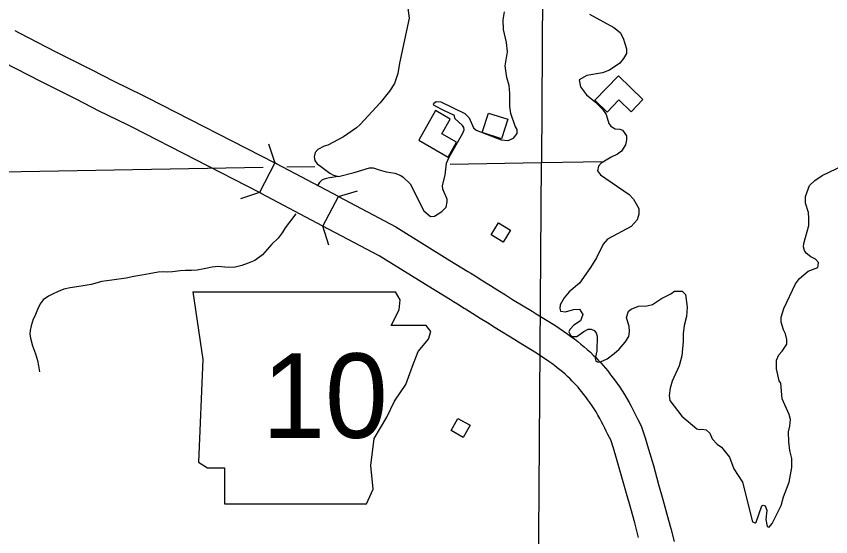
# Model space of a CAD drawing. Extents: x -19 to 366, y -4 to 359.
# Drawn here: x 137.635 to 138.792, y 198.536 to 199.276 of the extents above; entities that cross this region are included whole.
import ezdxf

# ---------------------------------------------------------------- set-up
doc = ezdxf.new("R2010")
doc.units = 0
for name, color, linetype in [('Level 10', 7, 'Continuous'), ('Level 21', 7, 'Continuous'), ('Level 35', 7, 'Continuous'), ('Level 37', 7, 'Continuous'), ('Level 5', 7, 'Continuous'), ('Level 56', 7, 'Continuous'), ('Level 57', 7, 'Continuous'), ('Level 60', 7, 'Continuous'), ('Level 9', 7, 'Continuous')]:
    doc.layers.add(name, color=color, linetype=linetype)

msp = doc.modelspace()

# ---------------------------------------------------------------- linework, layer by layer
at = {"layer": 'Level 10'}
for p, q in [((138.0017, 199.0671), (137.9801, 199.025)), ((138.0702, 198.9774), (138.0924, 199.0193)), ((138.2506, 198.9286), (138.2761, 198.913)), ((138.2761, 198.913), (138.2805, 198.9104)), ((138.2515, 198.8726), (138.226, 198.8881)), ((138.2557, 198.87), (138.2515, 198.8726))]:
    msp.add_line(p, q, dxfattribs=at)
for points in [[(137.6326, 199.2552), (137.6386, 199.252), (137.6909, 199.2251), (137.7418, 199.1993), (137.7733, 199.1833), (137.8137, 199.1635), (137.8206, 199.16), (138.0017, 199.0671)], [(137.9801, 199.025), (137.7991, 199.1178), (137.7925, 199.1211), (137.7522, 199.1409), (137.7204, 199.1571), (137.6694, 199.183), (137.6167, 199.21)], [(138.0924, 199.0193), (138.0043, 199.0658), (138.0017, 199.0671)], [(138.0702, 198.9774), (137.9825, 199.0238), (137.9801, 199.025)], [(138.0924, 199.0193), (138.174, 198.9762), (138.2506, 198.9286)], [(138.226, 198.8881), (138.1504, 198.9351), (138.0702, 198.9774)], [(138.2805, 198.9104), (138.2865, 198.9067), (138.2959, 198.9008)], [(138.2959, 198.9008), (138.2977, 198.8997), (138.3083, 198.8932), (138.3189, 198.8865), (138.3295, 198.8799), (138.3399, 198.8734), (138.3677, 198.8564), (138.3733, 198.853), (138.3996, 198.8366), (138.4181, 198.824), (138.4228, 198.8207), (138.4276, 198.8173), (138.4324, 198.8137), (138.437, 198.8099), (138.4416, 198.8061), (138.446, 198.8022), (138.4504, 198.7982), (138.4545, 198.7942), (138.458, 198.7907), (138.4616, 198.7871), (138.4651, 198.7833), (138.4685, 198.7795), (138.4718, 198.7757), (138.475, 198.7717), (138.4782, 198.7677), (138.481, 198.7639), (138.4846, 198.7592), (138.4884, 198.754), (138.492, 198.7488), (138.4955, 198.7435), (138.4989, 198.738), (138.5021, 198.7325), (138.5053, 198.727), (138.5082, 198.7215), (138.5106, 198.7168), (138.513, 198.7121), (138.5153, 198.7074), (138.5177, 198.7028), (138.52, 198.6982), (138.5229, 198.6922), (138.5284, 198.6764), (138.5331, 198.6607), (138.5399, 198.6371), (138.5473, 198.6102), (138.5532, 198.5888), (138.5589, 198.5684), (138.5646, 198.5476), (138.5695, 198.5293)], [(138.2711, 198.8605), (138.2616, 198.8664), (138.2557, 198.87)], [(138.5189, 198.5351), (138.5133, 198.5558), (138.5076, 198.5761), (138.5017, 198.5976), (138.4943, 198.6243), (138.4877, 198.6473), (138.4833, 198.6618), (138.4792, 198.6739), (138.4776, 198.6771), (138.4753, 198.6816), (138.473, 198.6861), (138.4708, 198.6906), (138.4685, 198.6951), (138.4662, 198.6995), (138.4637, 198.7043), (138.4611, 198.7089), (138.4584, 198.7135), (138.4557, 198.7179), (138.4527, 198.7223), (138.4498, 198.7266), (138.4467, 198.7308), (138.4433, 198.7353), (138.4406, 198.7389), (138.4381, 198.7421), (138.4355, 198.7453), (138.4328, 198.7484), (138.4301, 198.7514), (138.4274, 198.7543), (138.4245, 198.7573), (138.4214, 198.7603), (138.4178, 198.7638), (138.4143, 198.767), (138.4107, 198.7702), (138.407, 198.7733), (138.4033, 198.7763), (138.3994, 198.7792), (138.3955, 198.7821), (138.3913, 198.7849), (138.3738, 198.797), (138.3483, 198.8127), (138.3429, 198.8161), (138.315, 198.8331), (138.3043, 198.8398), (138.2938, 198.8464), (138.2833, 198.853), (138.2728, 198.8595), (138.2711, 198.8605)]]:
    msp.add_lwpolyline(points, dxfattribs=at)
at = {"layer": 'Level 21'}
for p, q in [((137.8853, 198.884), (137.8997, 198.7879)), ((138.1801, 198.8728), (138.1735, 198.8839)), ((138.1785, 198.8584), (138.1801, 198.8728)), ((138.1673, 198.836), (138.1785, 198.8584)), ((138.217, 198.836), (138.1673, 198.836)), ((138.2234, 198.8279), (138.217, 198.836)), ((138.2202, 198.8167), (138.2234, 198.8279)), ((138.2057, 198.7991), (138.2202, 198.8167)), ((137.8997, 198.7879), (137.8933, 198.6421)), ((138.1977, 198.7783), (138.2057, 198.7991)), ((138.1881, 198.7526), (138.1977, 198.7783)), ((138.1721, 198.7286), (138.1881, 198.7526)), ((138.1609, 198.7062), (138.1721, 198.7286)), ((138.1433, 198.6757), (138.1609, 198.7062)), ((138.1385, 198.6373), (138.1433, 198.6757)), ((137.8933, 198.6421), (137.9062, 198.6341)), ((138.1417, 198.6037), (138.1385, 198.6373)), ((137.9062, 198.6341), (137.9302, 198.6341)), ((137.9302, 198.6341), (137.9302, 198.5828)), ((138.132, 198.5828), (138.1417, 198.6037)), ((137.9302, 198.5828), (138.132, 198.5828))]:
    msp.add_line(p, q, dxfattribs=at)
msp.add_lwpolyline([(137.8853, 198.884), (138.1735, 198.8839)], dxfattribs=at)
at = {"layer": 'Level 35'}
for points in [[(138.0924, 199.0481), (138.0797, 199.0462), (138.0754, 199.0452), (138.0718, 199.0441), (138.069, 199.043), (138.0654, 199.0394), (138.0626, 199.035)], [(138.0318, 198.995), (138.0168, 198.9752), (138.0123, 198.968), (138.0066, 198.9601), (137.9979, 198.9518), (137.9842, 198.9366), (137.9736, 198.9287), (137.9641, 198.9246), (137.9551, 198.9216), (137.9437, 198.9186), (137.9309, 198.919), (137.9214, 198.9202), (137.9127, 198.9191), (137.9017, 198.9168), (137.8915, 198.915), (137.8836, 198.9146), (137.8749, 198.9146), (137.8673, 198.9139), (137.8567, 198.9124), (137.8496, 198.9121), (137.8439, 198.9125), (137.8363, 198.9121), (137.8235, 198.9095), (137.8129, 198.9077), (137.8015, 198.9058), (137.7906, 198.9036), (137.7701, 198.9006), (137.7562, 198.8988), (137.741, 198.8943), (137.7267, 198.892), (137.7111, 198.8898), (137.7021, 198.8879), (137.6941, 198.8846), (137.6862, 198.8808), (137.6805, 198.8778), (137.6729, 198.8725), (137.6684, 198.8672), (137.6646, 198.8589), (137.6608, 198.8494), (137.6585, 198.8452), (137.6558, 198.8357), (137.6543, 198.8293), (137.6539, 198.8244), (137.6546, 198.8183), (137.6576, 198.8073), (137.6617, 198.7959), (137.6647, 198.7867), (137.6662, 198.7791), (137.6677, 198.7704)]]:
    msp.add_lwpolyline(points, dxfattribs=at)
at = {"layer": 'Level 37'}
for points in [[(137.993, 199.0942), (138.0017, 199.0671)], [(137.98, 199.025), (137.953, 199.0163)], [(138.0924, 199.0193), (138.1195, 199.0277)], [(138.0786, 198.9503), (138.0702, 198.9774)]]:
    msp.add_lwpolyline(points, dxfattribs=at)
at = {"layer": 'Level 5'}
for points in [[(138.3824, 199.3103), (138.3811, 199.0679)], [(138.2509, 199.0656), (138.3811, 199.0679)], [(138.3737, 198.0753), (138.3811, 199.0679)], [(138.3811, 199.0679), (138.4699, 199.0693)], [(137.3768, 199.0505), (137.9853, 199.061)], [(138.019, 199.0616), (138.059, 199.0623)]]:
    msp.add_lwpolyline(points, dxfattribs=at)
at = {"layer": 'Level 56'}
for points in [[(138.3199, 198.982), (138.3366, 198.9716), (138.3263, 198.9548), (138.3095, 198.9651)], [(138.2793, 198.6945), (138.2697, 198.6772), (138.2525, 198.6869), (138.2621, 198.7041)]]:
    msp.add_lwpolyline(points, close=True, dxfattribs=at)
at = {"layer": 'Level 57'}
for points in [[(138.4567, 199.1563), (138.474, 199.1395), (138.4909, 199.1568), (138.5082, 199.14), (138.525, 199.1573), (138.4904, 199.1909)], [(138.2483, 199.0756), (138.2603, 199.0966), (138.2393, 199.1085), (138.2513, 199.1295), (138.2303, 199.1415), (138.2064, 199.0995)], [(138.2965, 199.1105), (138.3054, 199.1381), (138.333, 199.1292), (138.3241, 199.1016)]]:
    msp.add_lwpolyline(points, close=True, dxfattribs=at)
at = {"layer": 'Level 60'}
for points in [[(146.7783, 1.697), (146.5788, 10.3131), (146.3785, 18.9294), (146.1776, 27.5458), (145.9759, 36.1624), (145.7736, 44.7791), (145.5705, 53.396), (145.3668, 62.013), (145.1624, 70.6301), (144.9572, 79.2474), (144.7514, 87.8648), (144.5449, 96.4823), (144.3377, 105.1), (144.1299, 113.7179), (143.9213, 122.3359), (143.712, 130.954), (143.5021, 139.5723), (143.2915, 148.1907), (143.0802, 156.8092), (142.8682, 165.4279), (142.6555, 174.0468), (142.4422, 182.6658), (142.2282, 191.2849), (142.0135, 199.9042), (141.7981, 208.5236), (141.582, 217.1432), (141.3653, 225.7629), (141.1479, 234.3828), (140.9298, 243.0028), (140.711, 251.623), (140.4916, 260.2433), (140.2715, 268.8638), (140.0508, 277.4844), (139.8293, 286.1051), (139.6072, 294.726), (139.3845, 303.3471), (139.161, 311.9683), (138.937, 320.5896), (138.7122, 329.2111), (138.4868, 337.8328), (138.2607, 346.4546)], [(139.4406, 1.5315), (139.2511, 10.1473), (139.0608, 18.7633), (138.8699, 27.3793), (138.6784, 35.9956), (138.4861, 44.6119), (138.2932, 53.2285), (138.0997, 61.8451), (137.9055, 70.4619), (137.7106, 79.0789), (137.5151, 87.6959), (137.319, 96.3132), (137.1221, 104.9306), (136.9247, 113.5481), (136.7265, 122.1658), (136.5278, 130.7836), (136.3283, 139.4016), (136.1282, 148.0197), (135.9275, 156.6379), (135.7261, 165.2564), (135.5241, 173.8749), (135.3214, 182.4936), (135.1181, 191.1125), (134.9141, 199.7315), (134.7095, 208.3506), (134.5043, 216.9699), (134.2984, 225.5894), (134.0919, 234.209), (133.8847, 242.8288), (133.6769, 251.4487), (133.4685, 260.0687), (133.2594, 268.6889), (133.0497, 277.3093), (132.8393, 285.9298), (132.6283, 294.5504), (132.4167, 303.1713), (132.2044, 311.7922), (131.9916, 320.4133), (131.778, 329.0346), (131.5639, 337.656), (131.3491, 346.2776)], [(0, 198.1326), (7.1014, 198.137), (14.2028, 198.1503), (21.3042, 198.1724), (28.4055, 198.2034), (35.5068, 198.2433), (42.6081, 198.292), (49.7092, 198.3496), (56.8103, 198.4161), (63.9113, 198.4913), (71.0123, 198.5755), (78.1131, 198.6685), (85.2137, 198.7704), (92.3143, 198.8811), (99.4147, 199.0007), (106.5149, 199.1291), (113.615, 199.2664), (120.7149, 199.4126), (127.8146, 199.5676), (134.9141, 199.7315), (142.0135, 199.9042), (149.1125, 200.0858), (156.2114, 200.2762), (163.31, 200.4755), (170.4084, 200.6837), (177.5065, 200.9007), (184.6043, 201.1265), (191.7018, 201.3612), (198.799, 201.6048), (205.896, 201.8572), (212.9926, 202.1185), (220.0888, 202.3886), (227.1848, 202.6676), (234.2803, 202.9554), (241.3755, 203.2521), (248.4704, 203.5576), (255.5648, 203.872), (262.6589, 204.1952), (269.7525, 204.5273), (276.8457, 204.8682), (283.9385, 205.218), (291.0309, 205.5766), (298.1228, 205.9441), (305.2142, 206.3204), (312.3051, 206.7056), (319.3956, 207.0996), (326.4856, 207.5024), (333.5751, 207.9141), (340.664, 208.3347)], [(0, 189.5162), (7.1121, 189.5206), (14.2243, 189.5339), (21.3364, 189.556), (28.4484, 189.5869), (35.5605, 189.6267), (42.6725, 189.6754), (49.7844, 189.7329), (56.8962, 189.7992), (64.0079, 189.8744), (71.1196, 189.9584), (78.2311, 190.0512), (85.3425, 190.1529), (92.4538, 190.2635), (99.5649, 190.3829), (106.6759, 190.5111), (113.7867, 190.6482), (120.8974, 190.7941), (128.0078, 190.9489), (135.1181, 191.1125), (142.2282, 191.2849), (149.338, 191.4662), (156.4476, 191.6563), (163.5569, 191.8553), (170.666, 192.0631), (177.7749, 192.2798), (184.8835, 192.5053), (191.9917, 192.7396), (199.0997, 192.9828), (206.2074, 193.2348), (213.3147, 193.4956), (220.4218, 193.7653), (227.5285, 194.0438), (234.6348, 194.3312), (241.7408, 194.6274), (248.8464, 194.9324), (255.9516, 195.2463), (263.0564, 195.569), (270.1608, 195.9005), (277.2648, 196.2409), (284.3683, 196.5901), (291.4715, 196.9481), (298.5741, 197.315), (305.6763, 197.6907), (312.7781, 198.0753), (319.8793, 198.4686), (326.9801, 198.8708), (334.0804, 199.2818), (341.1801, 199.7017)]]:
    msp.add_spline(points, degree=3, dxfattribs=at)
at = {"layer": 'Level 9'}
for points in [[(138.0915, 199.4106), (138.0999, 199.3936), (138.1041, 199.3822), (138.1273, 199.3459), (138.1451, 199.3258), (138.1872, 199.293), (138.1911, 199.2873), (138.193, 199.2729), (138.1789, 199.2091), (138.1767, 199.1943), (138.1722, 199.1799), (138.1651, 199.1692), (138.1515, 199.1528), (138.1231, 199.1218)], [(138.2431, 199.1414), (138.2283, 199.149), (138.2272, 199.1505), (138.2279, 199.152), (138.2313, 199.1543), (138.2377, 199.1539), (138.2718, 199.1374), (138.2779, 199.1313), (138.2844, 199.1169), (138.2882, 199.1139), (138.3238, 199.1), (138.3333, 199.0993), (138.3412, 199.1024), (138.3461, 199.1088), (138.3461, 199.1145), (138.3434, 199.1194), (138.3373, 199.1376), (138.3361, 199.1475), (138.336, 199.1657), (138.3348, 199.1774), (138.3317, 199.1888), (138.3294, 199.2051), (138.3327, 199.2252), (138.3312, 199.2385), (138.3269, 199.2567), (138.3265, 199.2707), (138.3283, 199.2821)], [(138.4493, 199.2784), (138.4838, 199.2596), (138.4926, 199.2524), (138.4971, 199.2445), (138.5017, 199.2293), (138.5018, 199.2229), (138.4976, 199.2156), (138.4924, 199.2088), (138.4773, 199.1992), (138.4678, 199.195), (138.4452, 199.1915), (138.4346, 199.1854), (138.4365, 199.1752), (138.4449, 199.1638), (138.4578, 199.1533), (138.4677, 199.1434), (138.473, 199.1362), (138.4765, 199.1234), (138.4795, 199.1192), (138.4856, 199.1158), (138.492, 199.1151), (138.4962, 199.1136), (138.5015, 199.1056), (138.5019, 199.0999), (138.5004, 199.0931), (138.4944, 199.084), (138.4887, 199.0798), (138.4797, 199.0752)], [(138.1416, 199.0603), (138.1503, 199.0573), (138.1603, 199.0546), (138.1724, 199.0528), (138.1811, 199.0494), (138.1845, 199.0471), (138.1944, 199.0377), (138.2138, 198.9991), (138.2233, 198.9911), (138.229, 198.9915), (138.2392, 198.998), (138.2456, 199.0045), (138.247, 199.0117), (138.2466, 199.0155), (138.2409, 199.0299), (138.2401, 199.0352), (138.2439, 199.05), (138.2461, 199.0667), (138.2498, 199.0755), (138.2693, 199.1097), (138.2712, 199.1142), (138.2704, 199.1176), (138.2685, 199.1203), (138.2575, 199.1301), (138.2571, 199.1347), (138.2431, 199.1414)], [(138.1231, 199.1218), (138.1178, 199.1172), (138.0993, 199.1042), (138.0771, 199.0924), (138.0718, 199.0909), (138.0631, 199.0863), (138.0593, 199.0821), (138.0578, 199.076), (138.0586, 199.0707), (138.062, 199.0658), (138.0666, 199.0628), (138.0799, 199.0526), (138.0852, 199.0496), (138.0924, 199.0481), (138.1147, 199.0535), (138.1366, 199.06), (138.1416, 199.0603)], [(138.4797, 199.0752), (138.4657, 199.0668), (138.462, 199.0626), (138.4605, 199.0561), (138.4647, 199.0501), (138.5056, 199.0222), (138.5117, 199.0158), (138.5193, 199.0025), (138.5194, 198.9945), (138.5167, 198.9862), (138.5081, 198.9767), (138.4745, 198.9587), (138.4685, 198.9519), (138.4591, 198.9325), (138.4505, 198.9184), (138.4347, 198.8963), (138.42, 198.8841), (138.4129, 198.8754), (138.4076, 198.8655), (138.4069, 198.8606), (138.408, 198.8568), (138.4152, 198.8557), (138.4265, 198.8591), (138.4349, 198.8592), (138.4394, 198.852), (138.4364, 198.8428), (138.427, 198.8367), (138.421, 198.8307), (138.4195, 198.8272), (138.4222, 198.8223), (138.4244, 198.8208), (138.4309, 198.8204), (138.441, 198.8277), (138.4474, 198.8308), (138.4516, 198.8308), (138.4558, 198.8293), (138.4588, 198.8259), (138.46, 198.8209), (138.4593, 198.8004), (138.4571, 198.7894), (138.4582, 198.7856), (138.462, 198.7841), (138.4647, 198.7845), (138.4741, 198.7891), (138.4843, 198.7964), (138.4911, 198.8025), (138.4997, 198.8124), (138.505, 198.8207), (138.5061, 198.8276), (138.5053, 198.8348), (138.5018, 198.8477), (138.5044, 198.8568), (138.5082, 198.8594), (138.5188, 198.8636), (138.5305, 198.8641), (138.5384, 198.866), (138.5516, 198.8744), (138.5648, 198.8813), (138.5697, 198.8851), (138.5807, 198.8851), (138.5853, 198.8802), (138.588, 198.8624), (138.5869, 198.8491), (138.5835, 198.8362)], [(138.7741, 198.9215), (138.7745, 198.9257), (138.7703, 198.9306), (138.7635, 198.934), (138.7571, 198.9389), (138.7548, 198.9427), (138.7532, 198.948), (138.7536, 198.9526), (138.7607, 198.9784), (138.761, 198.9886), (138.7602, 198.9966), (138.756, 199.0102), (138.756, 199.0193), (138.7619, 199.0349), (138.7691, 199.0422), (138.7796, 199.0494), (138.8212, 199.0693)], [(138.5835, 198.8362), (138.5821, 198.8244), (138.5821, 198.8134), (138.5803, 198.7929), (138.5766, 198.7789), (138.5665, 198.7572), (138.5635, 198.7474), (138.5624, 198.7367), (138.5632, 198.7295), (138.5803, 198.7076), (138.6016, 198.6895), (138.605, 198.6887), (138.6087, 198.6891), (138.6148, 198.688), (138.6201, 198.6831), (138.6236, 198.6751), (138.6304, 198.6676), (138.6368, 198.6634), (138.6482, 198.649), (138.6544, 198.6324), (138.6665, 198.6138), (138.6808, 198.5574), (138.6846, 198.5559), (138.6861, 198.5566), (138.6939, 198.5798), (138.6958, 198.5809), (138.6988, 198.5798), (138.7011, 198.5737), (138.6997, 198.5605), (138.7016, 198.5506), (138.7042, 198.5495), (138.7088, 198.5548), (138.7215, 198.5807), (138.7249, 198.5928), (138.7327, 198.6137), (138.7368, 198.6346), (138.7367, 198.6475), (138.734, 198.6588), (138.7325, 198.671), (138.732, 198.685), (138.7339, 198.6934), (138.7346, 198.7025), (138.7327, 198.7097), (138.7228, 198.732), (138.7208, 198.7544), (138.7185, 198.7578), (138.715, 198.7749), (138.715, 198.787), (138.7183, 198.7946), (138.7228, 198.7999), (138.7296, 198.8098), (138.7296, 198.8163), (138.7277, 198.8246), (138.7246, 198.8303), (138.7215, 198.8409), (138.7215, 198.8481), (138.7252, 198.8606), (138.7417, 198.8952), (138.7477, 198.9028), (138.7598, 198.9135), (138.7734, 198.9185), (138.7741, 198.9215)]]:
    msp.add_lwpolyline(points, dxfattribs=at)

# ---------------------------------------------------------------- texts
at = {"layer": 'Level 21'}
msp.add_text('10', height=0.12, dxfattribs=at).set_placement((137.984, 198.6766))

doc.saveas('drawing.dxf')
